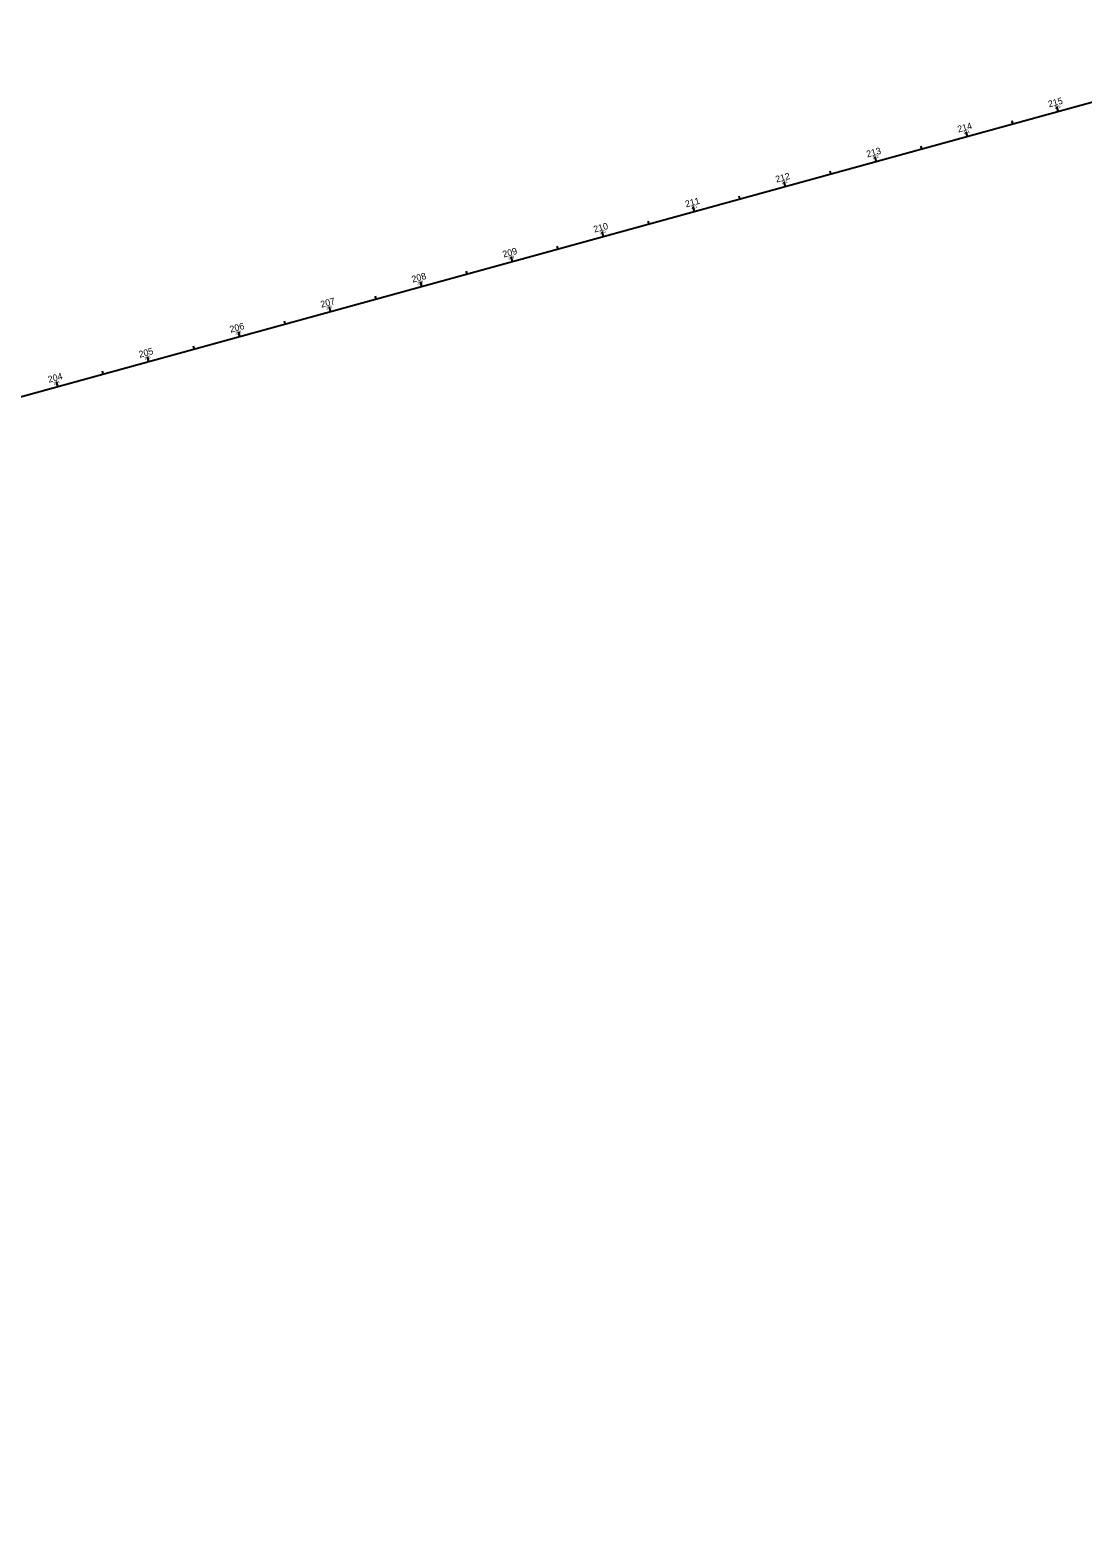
# Model space of a CAD drawing. Extents: x 2129507 to 2138391, y 657622 to 659877.
# Drawn here: x 2133942 to 2135058, y 657717 to 659316 of the extents above; entities that cross this region are included whole.
import ezdxf

# ---------------------------------------------------------------- set-up
doc = ezdxf.new("R2010")
doc.units = 0
for name, color, linetype in [('Default', 7, 'Continuous'), ('GE_X_Alignment_1000_Stations', 7, 'Continuous'), ('GE_X_Alignment_100_Stations', 7, 'Continuous'), ('GE_X_Alignment_500_Stations', 7, 'Continuous'), ('GE_X_CL_20', 7, 'Continuous'), ('MT_P_CL_20', 7, 'Continuous')]:
    doc.layers.add(name, color=color, linetype=linetype)

msp = doc.modelspace()

# ---------------------------------------------------------------- linework, layer by layer
at = {"layer": 'Default'}
for centre in [(2135032.3, 659229.7), (2135032.3, 659229.7), (2134935.9, 659203.2), (2134839.4, 659176.7), (2134743, 659150.1), (2134646.6, 659123.6), (2134550.2, 659097.1), (2134550.2, 659097.1), (2134550.2, 659097.1), (2134453.8, 659070.5), (2134357.4, 659044), (2134260.9, 659017.5), (2134164.5, 658990.9), (2134068.1, 658964.4), (2134068.1, 658964.4), (2133971.7, 658937.8)]:
    msp.add_circle(centre, 0.0000833, dxfattribs=at)
at = {"layer": 'GE_X_Alignment_1000_Stations'}
for p, q in [((2135032.3, 659229.7), (2135031.5, 659232.6)), ((2134550.2, 659097.1), (2134548.9, 659101.9)), ((2134068.1, 658964.4), (2134067.3, 658967.3))]:
    msp.add_line(p, q, dxfattribs=at)
at = {"layer": 'GE_X_Alignment_100_Stations'}
for p, q in [((2135032.3, 659229.7), (2135030.9, 659234.6)), ((2134984.1, 659216.5), (2134983.3, 659219.4)), ((2134935.9, 659203.2), (2134934.5, 659208)), ((2134887.6, 659189.9), (2134886.8, 659192.8)), ((2134839.4, 659176.7), (2134838.1, 659181.5)), ((2134743, 659150.1), (2134741.7, 659155)), ((2134791.2, 659163.4), (2134790.4, 659166.3)), ((2134694.8, 659136.9), (2134694, 659139.8)), ((2134646.6, 659123.6), (2134645.3, 659128.4)), ((2134598.4, 659110.3), (2134597.6, 659113.2)), ((2134550.2, 659097.1), (2134548.9, 659101.9)), ((2134453.8, 659070.5), (2134452.4, 659075.4)), ((2134502, 659083.8), (2134501.2, 659086.7)), ((2134405.6, 659057.3), (2134404.8, 659060.2)), ((2134357.4, 659044), (2134356, 659048.8)), ((2134309.2, 659030.7), (2134308.4, 659033.6)), ((2134260.9, 659017.5), (2134259.6, 659022.3)), ((2134164.5, 658990.9), (2134163.2, 658995.7)), ((2134212.7, 659004.2), (2134211.9, 659007.1)), ((2134116.3, 658977.7), (2134115.5, 658980.5)), ((2134068.1, 658964.4), (2134066.8, 658969.2)), ((2134019.9, 658951.1), (2134019.1, 658954)), ((2133971.7, 658937.8), (2133970.4, 658942.7))]:
    msp.add_line(p, q, dxfattribs=at)
at = {"layer": 'GE_X_Alignment_500_Stations'}
for p, q in [((2135032.3, 659229.7), (2135030.9, 659234.6)), ((2134935.9, 659203.2), (2134935.1, 659206.1)), ((2134839.4, 659176.7), (2134838.6, 659179.6)), ((2134743, 659150.1), (2134742.2, 659153)), ((2134646.6, 659123.6), (2134645.8, 659126.5)), ((2134550.2, 659097.1), (2134548.9, 659101.9)), ((2134453.8, 659070.5), (2134453, 659073.4)), ((2134357.4, 659044), (2134356.6, 659046.9)), ((2134260.9, 659017.5), (2134260.2, 659020.4)), ((2134164.5, 658990.9), (2134163.7, 658993.8)), ((2134068.1, 658964.4), (2134066.8, 658969.2)), ((2133971.7, 658937.8), (2133970.9, 658940.7))]:
    msp.add_line(p, q, dxfattribs=at)
at = {"layer": 'GE_X_CL_20'}
for p, q in [((2129536.9, 657717.3), (2135344.6, 659315.7)), ((2134984.1, 659216.5), (2134983.5, 659218.4)), ((2135032.3, 659229.7), (2135031.7, 659231.7)), ((2134935.9, 659203.2), (2134935.3, 659205.1)), ((2134887.6, 659189.9), (2134887.1, 659191.9)), ((2134839.4, 659176.7), (2134838.9, 659178.6)), ((2134743, 659150.1), (2134742.5, 659152.1)), ((2134791.2, 659163.4), (2134790.7, 659165.3)), ((2134694.8, 659136.9), (2134694.3, 659138.8)), ((2134646.6, 659123.6), (2134646.1, 659125.5)), ((2134598.4, 659110.3), (2134597.9, 659112.3)), ((2134550.2, 659097.1), (2134549.7, 659099)), ((2134453.8, 659070.5), (2134453.2, 659072.5)), ((2134502, 659083.8), (2134501.5, 659085.7)), ((2134405.6, 659057.3), (2134405, 659059.2)), ((2134357.4, 659044), (2134356.8, 659045.9)), ((2134309.2, 659030.7), (2134308.6, 659032.7)), ((2134260.9, 659017.5), (2134260.4, 659019.4)), ((2134164.5, 658990.9), (2134164, 658992.9)), ((2134212.7, 659004.2), (2134212.2, 659006.1)), ((2134116.3, 658977.7), (2134115.8, 658979.6)), ((2134068.1, 658964.4), (2134067.6, 658966.3)), ((2134019.9, 658951.1), (2134019.4, 658953)), ((2133971.7, 658937.8), (2133971.2, 658939.8))]:
    msp.add_line(p, q, dxfattribs=at)
at = {"layer": 'MT_P_CL_20'}
msp.add_line((2129536.9, 657717.3), (2135344.6, 659315.7), dxfattribs=at)

# ---------------------------------------------------------------- texts
at = {"layer": 'GE_X_Alignment_1000_Stations'}
msp.add_text('210', height=7, rotation=15.3886, dxfattribs=at).set_placement((2134540.6, 659101))
at = {"layer": 'GE_X_Alignment_100_Stations'}
for s, p in [('215', (2135022.6, 659233.7)), ('214', (2134926.4, 659207.1)), ('213', (2134829.9, 659180.7)), ('212', (2134733.5, 659154)), ('211', (2134637.8, 659127.7)), ('210', (2134540.6, 659101)), ('209', (2134444.2, 659074.5)), ('208', (2134347.8, 659048)), ('207', (2134251.2, 659021.4)), ('206', (2134154.9, 658994.9)), ('205', (2134058.5, 658968.3)), ('204', (2133962.2, 658941.8))]:
    msp.add_text(s, height=7, rotation=15.3886, dxfattribs=at).set_placement(p)
at = {"layer": 'GE_X_Alignment_500_Stations'}
for s, p in [('215', (2135022.6, 659233.7)), ('210', (2134540.6, 659101)), ('205', (2134058.5, 658968.3))]:
    msp.add_text(s, height=7, rotation=15.3886, dxfattribs=at).set_placement(p)
at = {"layer": 'GE_X_CL_20'}
for s, p in [('215', (2135028.7, 659231.9)), ('214', (2134932.3, 659205.3)), ('213', (2134835.8, 659178.8)), ('212', (2134739.4, 659152.3)), ('211', (2134643.5, 659125.9)), ('210', (2134546.5, 659099.2)), ('209', (2134449.5, 659072.5)), ('208', (2134353.1, 659045.9)), ('207', (2134256.6, 659019.4)), ('206', (2134160.2, 658992.9)), ('205', (2134063.8, 658966.3)), ('204', (2133967.5, 658939.8))]:
    msp.add_text(s, height=2.8, rotation=15.3886, dxfattribs=at).set_placement(p)

doc.saveas('drawing.dxf')
